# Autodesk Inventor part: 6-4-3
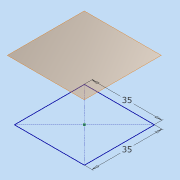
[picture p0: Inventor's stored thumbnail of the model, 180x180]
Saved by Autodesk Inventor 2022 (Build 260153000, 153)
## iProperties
Created: 2021-07
Part Number: 6-4-3
Material: 一般
Document SubType Name: Modeling
Designer: DesignLab
Density: 1 g/cm^3
Appearance: 既定
Author: DesignLab
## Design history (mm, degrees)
sketch "スケッチ1"
  geometry: L1 (-17.5, -17.5)-(17.5, -17.5); L2 (17.5, -17.5)-(17.5, 17.5); L3 (17.5, 17.5)-(-17.5, 17.5); L4 (-17.5, 17.5)-(-17.5, -17.5); L5 (-17.5, -17.5)-(17.5, 17.5); L6 (17.5, -17.5)-(-17.5, 17.5); 1 further point
  constraints: 12 end point, 2 midpoint, 2 parallel, 1 horizontal, 1 perpendicular
  dimensions: "d0" = 35 distance of L3.end L2.end; "d1" = 35 distance of L2.end L1.end
node "作業平面1"
